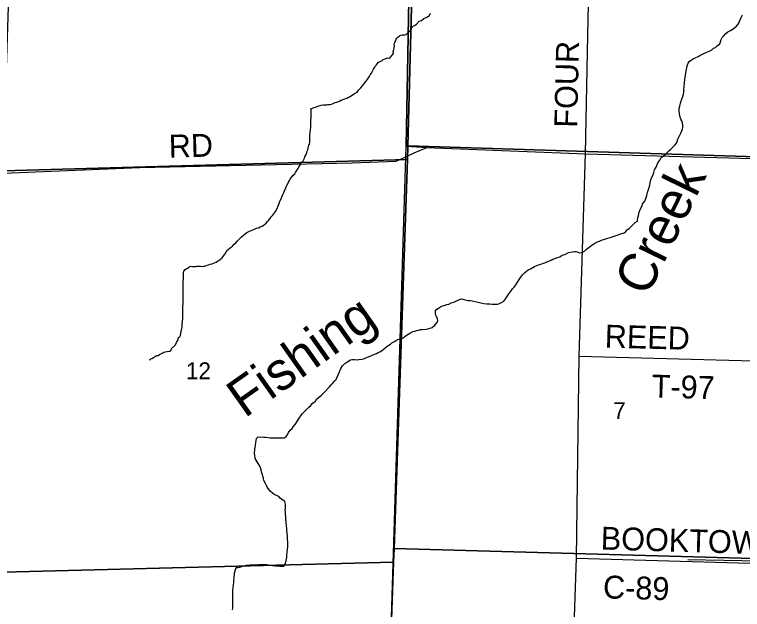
# Model space of a CAD drawing. Extents: x 1588073 to 2013523, y 1090242 to 1357120.
# Drawn here: x 1775971 to 1785512, y 1238801 to 1246602 of the extents above; entities that cross this region are included whole.
import ezdxf

# ---------------------------------------------------------------- set-up
doc = ezdxf.new("R2010")
doc.units = 0
for name, color, linetype in [('GM_X_County_Road', 7, 'Continuous'), ('GM_X_County_Road_Text', 7, 'Continuous'), ('GM_X_Minor_River', 7, 'Continuous'), ('GM_X_Minor_River_Text', 7, 'Continuous'), ('GM_X_Section', 7, 'Continuous'), ('GM_X_Section_Text', 7, 'Continuous'), ('GM_X_Township', 7, 'Continuous'), ('GM_X_Township_Road', 7, 'Continuous'), ('GM_X_Township_Road_Text', 7, 'Continuous')]:
    doc.layers.add(name, color=color, linetype=linetype)

msp = doc.modelspace()

# ---------------------------------------------------------------- linework, layer by layer
at = {"layer": 'GM_X_County_Road'}
for points in [[(1783454.6, 1244777.1), (1783483.6, 1246333.5), (1783512.5, 1247549.2), (1783520.4, 1247879.8), (1783535, 1248540.5), (1783603.1, 1249160.2), (1783630.9, 1249895)], [(1781100, 1244734.5), (1781211, 1244789.1), (1781374.5, 1244858.9), (1783454.6, 1244777.1)], [(1783121.2, 1229450.4), (1783155.4, 1234094.4), (1783337.6, 1239471.4), (1783374, 1242120.5), (1783454.6, 1244777.1)], [(1783454.6, 1244777.1), (1789714, 1244599.1), (1794098.9, 1244507.8)], [(1773346.4, 1244497.8), (1775825.4, 1244523.5), (1777610.5, 1244596.7), (1780396.8, 1244658.8), (1780972.6, 1244678.2), (1781100, 1244734.5)], [(1783337.6, 1239471.4), (1786668.9, 1239378.6), (1793915.9, 1239279.6)]]:
    msp.add_lwpolyline(points, dxfattribs=at)
at = {"layer": 'GM_X_Minor_River'}
msp.add_line((1787914.9, 1239390.1), (1784794.5, 1239452.2), dxfattribs=at)
for points in [[(1780699.6, 1245923.9), (1780713.6, 1245942), (1780725.6, 1245956.1), (1780737.5, 1245974.2), (1780751.5, 1245982.3), (1780765.5, 1245986.3), (1780789.5, 1245998.4), (1780801.5, 1246014.5), (1780865.4, 1246032.8), (1780881.4, 1246030.8), (1780895.4, 1246040.9), (1780925.4, 1246073.1), (1780937.3, 1246091.2), (1780935.3, 1246111.2), (1780937.2, 1246125.3), (1780943.2, 1246149.4), (1780945.1, 1246165.4), (1780949.1, 1246187.5), (1780949, 1246207.6), (1780953, 1246225.6), (1780958.9, 1246243.7), (1780962.9, 1246257.7), (1780972.8, 1246277.8), (1780980.8, 1246291.9), (1780992.8, 1246306), (1781014.7, 1246322.1), (1781032.7, 1246332.2), (1781052.7, 1246338.2), (1781086.8, 1246334.3), (1781104.7, 1246340.4), (1781142.7, 1246378.6), (1781160.6, 1246392.8), (1781172.6, 1246410.8), (1781176.5, 1246432.9), (1781196.5, 1246451), (1781220.5, 1246461.1), (1781238.5, 1246477.2), (1781256.4, 1246495.3), (1781266.4, 1246509.4), (1781288.4, 1246519.5), (1781306.4, 1246525.6), (1781334.3, 1246551.8), (1781376.3, 1246567.9), (1781396.3, 1246580), (1781410.2, 1246590.1), (1781424.2, 1246620.2)], [(1784470.9, 1244743.8), (1784497.1, 1244767.7), (1784519.2, 1244787.7), (1784549.5, 1244817.6), (1784569.6, 1244833.5), (1784595.8, 1244857.4), (1784626, 1244889.3), (1784646.2, 1244915.2), (1784658.4, 1244937.2), (1784664.6, 1244967.3), (1784691, 1245021.3), (1784705.2, 1245045.3), (1784719.4, 1245075.3), (1784727.5, 1245097.3), (1784731.7, 1245123.3), (1784731.9, 1245151.4), (1784728.1, 1245183.6), (1784716.3, 1245209.7), (1784704.4, 1245231.8), (1784694.6, 1245258), (1784686.8, 1245298.2), (1784683.1, 1245340.3), (1784683.3, 1245376.4), (1784689.5, 1245400.5), (1784699.8, 1245438.5), (1784705.9, 1245458.5), (1784718.1, 1245490.6), (1784730.4, 1245528.6), (1784738.6, 1245556.6), (1784742.8, 1245584.7), (1784745, 1245616.8), (1784749.3, 1245656.9), (1784753.6, 1245703), (1784757.9, 1245753.1), (1784764.3, 1245801.2), (1784768.5, 1245843.3), (1784776.8, 1245879.4), (1784783, 1245911.4), (1784791.2, 1245941.5), (1784801.4, 1245965.5), (1784815.6, 1245987.5), (1784871.9, 1246025.2), (1784891.9, 1246033.1), (1784930.1, 1246050.9), (1784952.2, 1246066.8), (1785014.5, 1246094.5), (1785046.6, 1246110.4), (1785068.7, 1246118.3), (1785104.9, 1246136.1), (1785131.1, 1246160), (1785159.2, 1246171.8), (1785181.3, 1246189.8), (1785215.6, 1246219.6), (1785225.7, 1246243.6), (1785232, 1246273.7), (1785246.1, 1246299.7), (1785262.3, 1246319.6), (1785294.6, 1246355.6), (1785322.7, 1246373.4), (1785356.9, 1246393.3), (1785389.1, 1246415.1), (1785415.3, 1246435), (1785435.4, 1246450.9), (1785455.6, 1246474.9), (1785469.7, 1246498.9), (1785479.9, 1246522.9), (1785492.1, 1246552.9), (1785504.3, 1246578.9), (1785514.5, 1246598.9)], [(1779336.2, 1243947.9), (1779354.1, 1243968), (1779366.1, 1243984.1), (1779380, 1244002.2), (1779392, 1244020.3), (1779411.9, 1244060.5), (1779425.8, 1244092.6), (1779437.7, 1244124.8), (1779449.7, 1244154.9), (1779465.6, 1244187), (1779477.5, 1244219.1), (1779489.5, 1244241.2), (1779501.4, 1244269.4), (1779509.3, 1244291.5), (1779525.2, 1244327.6), (1779535.2, 1244349.7), (1779545.1, 1244369.8), (1779553.1, 1244383.9), (1779563.1, 1244404), (1779573, 1244426.1), (1779583, 1244442.1), (1779616.9, 1244492.4), (1779642.8, 1244514.5), (1779652.8, 1244528.6), (1779662.7, 1244544.7), (1779676.7, 1244564.8), (1779688.7, 1244582.9), (1779698.6, 1244605), (1779712.6, 1244627.1), (1779718.5, 1244651.2), (1779736.5, 1244663.3), (1779750.4, 1244675.3), (1779772.3, 1244719.5), (1779774.3, 1244735.6), (1779790.2, 1244757.7), (1779798.2, 1244777.8), (1779802.2, 1244791.8), (1779806.1, 1244809.9), (1779814.1, 1244828), (1779820, 1244848.1), (1779826, 1244870.1), (1779829.9, 1244890.2), (1779835.9, 1244904.3), (1779839.8, 1244926.3), (1779839.6, 1245010.6), (1779841.6, 1245028.6), (1779845.5, 1245048.7), (1779847.5, 1245062.8), (1779849.4, 1245086.8), (1779851.4, 1245100.9), (1779853.3, 1245116.9), (1779855.3, 1245135), (1779855, 1245229.3), (1779857, 1245243.3), (1779857, 1245261.4), (1779860.9, 1245289.5), (1779860.8, 1245305.5), (1779860.8, 1245321.6), (1779860.8, 1245335.6), (1779858.7, 1245351.6), (1779852.7, 1245367.7), (1779884.7, 1245377.8), (1779914.7, 1245385.9), (1779960.6, 1245406.1), (1779988.6, 1245414.2), (1780018.6, 1245416.3), (1780034.6, 1245418.4), (1780062.7, 1245418.5), (1780078.6, 1245420.5), (1780104.7, 1245424.6), (1780124.7, 1245428.7), (1780146.6, 1245434.8), (1780172.6, 1245448.9), (1780194.6, 1245453), (1780208.6, 1245457.1), (1780228.6, 1245467.1), (1780252.6, 1245477.2), (1780288.6, 1245491.4), (1780326.5, 1245507.6), (1780346.5, 1245517.6), (1780362.5, 1245523.7), (1780382.5, 1245537.8), (1780412.5, 1245556), (1780428.4, 1245566.1), (1780442.4, 1245574.1), (1780460.4, 1245586.2), (1780480.4, 1245610.3), (1780494.3, 1245624.4), (1780510.3, 1245640.5), (1780532.2, 1245668.7), (1780560.1, 1245702.9), (1780576.1, 1245723), (1780592.1, 1245745.1), (1780610, 1245771.2), (1780620, 1245787.3), (1780633.9, 1245809.4), (1780649.8, 1245835.5), (1780661.8, 1245857.6), (1780675.7, 1245883.8), (1780691.7, 1245909.9), (1780699.6, 1245923.9)], [(1781730.9, 1242831.3), (1781811.3, 1242870.9), (1781833.3, 1242872.8), (1781861.3, 1242864.6), (1781891.3, 1242858.4), (1781917.3, 1242854.2), (1781943.3, 1242852), (1781967.3, 1242845.8), (1781987.3, 1242841.7), (1782063.3, 1242825.2), (1782123.3, 1242812.8), (1782163.3, 1242808.5), (1782199.3, 1242806.3), (1782227.3, 1242804.1), (1782269.4, 1242803.8), (1782305.4, 1242805.6), (1782329.5, 1242811.4), (1782355.6, 1242825.3), (1782383.8, 1242845.2), (1782410, 1242877.1), (1782424.2, 1242899.1), (1782448.5, 1242939.1), (1782464.6, 1242959.1), (1782480.8, 1242981), (1782499, 1243003), (1782521.2, 1243028.9), (1782543.4, 1243058.9), (1782565.6, 1243090.8), (1782581.8, 1243118.8), (1782594, 1243138.8), (1782630.4, 1243188.7), (1782658.6, 1243218.6), (1782704.9, 1243252.4), (1782733, 1243268.3), (1782785.2, 1243296.1), (1782853.5, 1243325.7), (1782883.6, 1243333.6), (1782903.7, 1243343.4), (1782923.8, 1243347.3), (1782947.9, 1243361.2), (1782984, 1243373), (1783006.1, 1243382.9), (1783026.2, 1243392.8), (1783054.3, 1243402.7), (1783086.4, 1243414.5), (1783116.5, 1243426.4), (1783136.6, 1243438.3), (1783160.7, 1243452.2), (1783184.8, 1243456), (1783233, 1243481.8), (1783281.1, 1243489.5), (1783311.2, 1243495.3), (1783331.2, 1243493.2), (1783353.2, 1243485.1), (1783379.1, 1243476.9), (1783409.2, 1243482.7), (1783441.4, 1243500.5), (1783467.6, 1243524.4), (1783501.8, 1243550.3), (1783540, 1243578.2), (1783578.2, 1243602), (1783612.4, 1243619.8), (1783640.5, 1243631.7), (1783666.6, 1243641.6), (1783722.8, 1243661.2), (1783805.1, 1243688.8), (1783855.2, 1243706.6), (1783919.4, 1243724.2), (1783959.6, 1243738), (1783981.7, 1243755.9), (1784005.9, 1243781.8), (1784028.1, 1243797.7), (1784066.3, 1243833.6), (1784106.6, 1243873.5), (1784136.8, 1243891.3), (1784136.9, 1243911.4), (1784141.1, 1243935.4), (1784155.4, 1243983.5), (1784157.6, 1244011.6), (1784165.8, 1244031.6), (1784184.1, 1244071.6), (1784198.2, 1244095.6), (1784202.4, 1244119.6), (1784234.7, 1244155.5), (1784251, 1244201.6), (1784259.2, 1244229.6), (1784263.3, 1244249.6), (1784265.5, 1244269.7), (1784279.8, 1244309.7), (1784300.2, 1244365.8), (1784304.3, 1244389.8), (1784308.5, 1244419.9), (1784320.8, 1244457.9), (1784341.1, 1244503.9), (1784351.3, 1244529.9), (1784359.5, 1244564), (1784379.8, 1244600), (1784404.2, 1244656), (1784428.5, 1244691.9), (1784446.7, 1244725.9), (1784470.9, 1244743.8)], [(1777742.3, 1242069.5), (1777748.3, 1242083.5), (1777768.3, 1242093.6), (1777794.3, 1242105.7), (1777832.2, 1242129.9), (1777852.2, 1242132), (1777872.2, 1242142.1), (1777898.2, 1242158.2), (1777930.1, 1242174.3), (1777946.1, 1242180.4), (1777972.1, 1242184.5), (1777994.1, 1242186.6), (1778012.1, 1242188.6), (1778022.1, 1242202.7), (1778030, 1242224.8), (1778066, 1242257), (1778080, 1242269.1), (1778093.9, 1242301.2), (1778115.8, 1242335.4), (1778121.7, 1242365.5), (1778137.7, 1242377.6), (1778147.7, 1242391.7), (1778151.6, 1242423.8), (1778155.5, 1242443.8), (1778165.4, 1242484), (1778169.4, 1242508.1), (1778169.3, 1242546.2), (1778173.2, 1242578.3), (1778175.1, 1242618.4), (1778177, 1242656.5), (1778174.9, 1242688.6), (1778174.7, 1242746.8), (1778178.7, 1242778.9), (1778180.6, 1242807), (1778180.5, 1242835.1), (1778182.4, 1242863.1), (1778182.3, 1242931.3), (1778180.2, 1242951.4), (1778180.2, 1242971.5), (1778182.1, 1242989.5), (1778180.1, 1243011.6), (1778182, 1243035.6), (1778181.8, 1243117.9), (1778183.7, 1243131.9), (1778183.6, 1243184.1), (1778185.6, 1243202.1), (1778187.5, 1243218.2), (1778191.5, 1243236.3), (1778205.4, 1243258.4), (1778263.3, 1243292.6), (1778281.3, 1243300.7), (1778301.4, 1243298.8), (1778345.4, 1243298.9), (1778359.4, 1243301), (1778375.4, 1243303), (1778393.4, 1243301.1), (1778407.4, 1243301.1), (1778427.4, 1243299.2), (1778441.4, 1243301.2), (1778459.4, 1243301.3), (1778475.4, 1243307.4), (1778495.4, 1243315.4), (1778511.4, 1243321.5), (1778535.4, 1243327.6), (1778561.4, 1243331.7), (1778577.4, 1243339.8), (1778591.4, 1243345.8), (1778615.4, 1243355.9), (1778631.3, 1243366), (1778649.3, 1243376.1), (1778671.3, 1243396.2), (1778691.3, 1243410.3), (1778715.2, 1243442.5), (1778729.1, 1243460.6), (1778741.1, 1243476.7), (1778755, 1243508.8), (1778771, 1243522.9), (1778803, 1243545.1), (1778826.9, 1243565.2), (1778850.9, 1243591.4), (1778870.8, 1243609.5), (1778890.8, 1243631.6), (1778914.7, 1243657.8), (1778940.7, 1243681.9), (1778976.6, 1243714.1), (1779014.5, 1243742.3), (1779048.5, 1243760.5), (1779074.5, 1243770.6), (1779094.5, 1243780.7), (1779116.5, 1243788.8), (1779140.4, 1243798.9), (1779168.4, 1243807), (1779192.4, 1243817.1), (1779214.4, 1243827.2), (1779232.4, 1243839.3), (1779246.4, 1243847.3), (1779270.3, 1243867.5), (1779288.3, 1243887.6), (1779300.3, 1243901.7), (1779318.2, 1243923.8), (1779336.2, 1243947.9)], [(1779258.3, 1241061.5), (1779294.3, 1241055.2), (1779322.3, 1241053.1), (1779388.4, 1241052.6), (1779408.4, 1241050.5), (1779438.4, 1241052.3), (1779466.4, 1241050.1), (1779486.5, 1241052), (1779506.5, 1241051.9), (1779530.6, 1241067.8), (1779548.8, 1241091.8), (1779563, 1241121.7), (1779583.2, 1241149.7), (1779609.4, 1241175.6), (1779623.6, 1241195.6), (1779647.8, 1241225.5), (1779666, 1241253.5), (1779678.2, 1241273.5), (1779692.3, 1241297.5), (1779708.5, 1241321.4), (1779722.7, 1241341.4), (1779740.8, 1241365.4), (1779761, 1241387.3), (1779785.2, 1241411.2), (1779829.5, 1241453.1), (1779853.7, 1241477), (1779871.9, 1241503), (1779916.2, 1241532.8), (1779934.4, 1241560.8), (1779992.8, 1241608.5), (1780017, 1241634.4), (1780047.2, 1241664.3), (1780081.5, 1241702.3), (1780101.6, 1241722.2), (1780119.8, 1241744.1), (1780139.9, 1241762.1), (1780170.2, 1241798), (1780184.4, 1241818), (1780196.5, 1241837.9), (1780214.8, 1241875.9), (1780227, 1241908), (1780249.4, 1241960), (1780269.7, 1241996), (1780301.9, 1242025.9), (1780340.1, 1242051.7), (1780374.3, 1242073.5), (1780400.4, 1242079.4), (1780428.4, 1242077.2), (1780464.4, 1242075), (1780484.5, 1242078.9), (1780522.5, 1242080.6), (1780550.6, 1242086.5), (1780576.7, 1242098.3), (1780596.8, 1242108.2), (1780632.9, 1242124.1), (1780657, 1242133.9), (1780713.3, 1242157.7), (1780737.4, 1242169.5), (1780757.4, 1242177.4), (1780781.6, 1242191.3), (1780825.8, 1242225.1), (1780856, 1242251.1), (1780898.3, 1242280.9), (1780918.4, 1242296.8), (1780950.6, 1242316.6), (1780970.7, 1242328.6), (1780996.8, 1242340.4), (1781020.9, 1242348.3), (1781047, 1242356.2), (1781067, 1242364.1), (1781087.2, 1242382), (1781115.3, 1242399.9), (1781139.5, 1242415.8), (1781161.6, 1242429.7), (1781189.7, 1242443.5), (1781215.8, 1242451.4), (1781241.9, 1242457.2), (1781265.9, 1242465.1), (1781294, 1242473), (1781320.1, 1242472.8), (1781366.1, 1242476.5), (1781386.2, 1242480.4), (1781420.3, 1242488.2), (1781444.4, 1242498.1), (1781478.6, 1242528), (1781510.9, 1242561.9), (1781521.1, 1242587.9), (1781513.2, 1242612), (1781501.4, 1242642.2), (1781489.6, 1242670.3), (1781487.7, 1242690.4), (1781489.9, 1242716.5), (1781506, 1242736.4), (1781526.2, 1242752.3), (1781552.3, 1242768.2), (1781578.4, 1242780.1), (1781602.5, 1242788), (1781636.6, 1242797.8), (1781662.7, 1242805.6), (1781692.8, 1242819.5), (1781730.9, 1242831.3)], [(1778828.7, 1238795.3), (1778830.9, 1238821.3), (1778833, 1238843.4), (1778833.2, 1238863.4), (1778833.6, 1238923.6), (1778833.9, 1238971.8), (1778832.1, 1238997.9), (1778832.5, 1239062.1), (1778838.8, 1239114.2), (1778843.1, 1239158.3), (1778845.3, 1239182.3), (1778847.5, 1239204.4), (1778851.6, 1239232.5), (1778853.8, 1239256.5), (1778856, 1239278.6), (1778862.1, 1239302.6), (1778868.3, 1239324.6), (1778876.4, 1239348.6), (1778902.5, 1239352.5), (1778924.6, 1239356.4), (1778948.6, 1239364.2), (1779006.8, 1239381.9), (1779052.9, 1239387.7), (1779099, 1239387.4), (1779167.1, 1239390.9), (1779201.1, 1239388.7), (1779231.1, 1239388.5), (1779251.2, 1239390.4), (1779271.2, 1239390.3), (1779321.2, 1239379.9), (1779353.2, 1239377.7), (1779387.2, 1239373.5), (1779421.2, 1239371.3), (1779449.3, 1239369.1), (1779479.3, 1239366.9), (1779501.3, 1239368.8), (1779521.6, 1239402.8), (1779538.1, 1239480.9), (1779538.2, 1239503), (1779542.6, 1239555.1), (1779551, 1239623.2), (1779553.3, 1239655.3), (1779553.4, 1239677.4), (1779549.7, 1239727.6), (1779548, 1239759.7), (1779538.5, 1239840), (1779538.6, 1239860.1), (1779534.9, 1239898.2), (1779531.1, 1239940.3), (1779527.4, 1239978.5), (1779525.6, 1240016.6), (1779523.9, 1240052.7), (1779522, 1240078.8), (1779520.2, 1240102.9), (1779522.3, 1240123), (1779524.5, 1240153), (1779522.7, 1240181.1), (1779512.9, 1240215.3), (1779451.2, 1240261.8), (1779433.3, 1240282), (1779375.4, 1240308.4), (1779351.5, 1240324.6), (1779321.6, 1240350.9), (1779297.8, 1240383.2), (1779283.9, 1240405.3), (1779272.1, 1240427.5), (1779258.2, 1240451.6), (1779240.4, 1240489.8), (1779232.6, 1240518), (1779224.8, 1240548.1), (1779219, 1240572.2), (1779209.2, 1240602.4), (1779201.3, 1240632.5), (1779193.5, 1240656.7), (1779179.7, 1240686.8), (1779165.8, 1240713), (1779124.2, 1240781.5), (1779118.5, 1240825.6), (1779116.7, 1240847.7), (1779119, 1240899.9), (1779123.2, 1240929.9), (1779127.4, 1240956), (1779133.6, 1240988), (1779137.8, 1241018.1), (1779144, 1241044.1), (1779166.2, 1241062.1), (1779190.2, 1241061.9), (1779218.2, 1241063.7), (1779238.2, 1241061.6), (1779258.3, 1241061.5)]]:
    msp.add_lwpolyline(points, dxfattribs=at)
at = {"layer": 'GM_X_Section'}
for points in [[(1781261.5, 1250000.7), (1781124.6, 1244880.7), (1781123.2, 1244700.6), (1775823, 1244552.7), (1776000.9, 1250072.6)], [(1786253.4, 1249852.8), (1786110.3, 1244724.8), (1781124.6, 1244880.7), (1781261.5, 1250000.7)], [(1781124.6, 1244880.7), (1786110.3, 1244724.8), (1785968.2, 1239458.7), (1780948.4, 1239599), (1781123.2, 1244700.6)], [(1775823, 1244552.7), (1781123.2, 1244700.6), (1780948.4, 1239599), (1780939, 1239420.9), (1775653, 1239287)], [(1785968.2, 1239458.7), (1785757.6, 1234139.3), (1780754.9, 1234157.3), (1780939, 1239420.9), (1780948.4, 1239599)], [(1780939, 1239420.9), (1780754.9, 1234157.3), (1780748.6, 1234119.3), (1775456.7, 1233993.5), (1775653, 1239287)]]:
    msp.add_lwpolyline(points, close=True, dxfattribs=at)
at = {"layer": 'GM_X_Township'}
for points in [[(1786336.9, 1260386.3), (1783657.7, 1260404.7), (1783297.9, 1260406), (1782450.2, 1260413.4), (1781290.9, 1260418.2), (1781295.9, 1257972.1), (1781293.6, 1257698.9), (1781293.1, 1255294.3), (1781244.3, 1252600.3), (1781193.8, 1249809.6), (1781165.4, 1248243.1), (1781104.5, 1244875.1), (1781374.5, 1244858.9), (1783454.6, 1244777.1), (1789714, 1244599.1)], [(1780849.5, 1236733), (1781100, 1244734.5), (1781104.5, 1244875.1), (1781165.4, 1248243.1)], [(1780849.5, 1236733), (1781100, 1244734.5), (1781104.5, 1244875.1), (1781374.5, 1244858.9), (1783454.6, 1244777.1), (1789714, 1244599.1), (1794098.9, 1244507.9), (1797984.2, 1244413.4), (1801960.9, 1244391.9)]]:
    msp.add_lwpolyline(points, dxfattribs=at)
at = {"layer": 'GM_X_Township_Road'}
for points in [[(1780849.5, 1236733), (1781100, 1244734.5)], [(1783374, 1242120.5), (1793989.1, 1241838.3)]]:
    msp.add_lwpolyline(points, dxfattribs=at)

# ---------------------------------------------------------------- texts
at = {"layer": 'GM_X_County_Road_Text'}
for s, rotation, p in [('FOUR', 88.71045, (1783345.5, 1245116)), ('RD', 1.48068, (1777995.8, 1244725.3)), ('BOOKTOWN', 358.34997, (1783651.9, 1239586.2)), ('C-89', 358.2847, (1783681.3, 1238947.2))]:
    msp.add_text(s, height=300, rotation=rotation, dxfattribs=at).set_placement(p)
at = {"layer": 'GM_X_Minor_River_Text'}
for s, height, rotation, p in [('Creek', 500.32, 63.93728, (1784264.4, 1242888.2)), ('Fishing', 500.3, 35.21788, (1778987, 1241302.9))]:
    msp.add_text(s, height=height, rotation=rotation, dxfattribs=at).set_placement(p)
at = {"layer": 'GM_X_Section_Text'}
for s, p in [('12', (1778216.7, 1241819.7)), ('7', (1783817.9, 1241297.2))]:
    msp.add_text(s, height=221, rotation=0.00001, dxfattribs=at).set_placement(p)
at = {"layer": 'GM_X_Township_Road_Text'}
for s, rotation, p in [('REED', 358.42333, (1783704.4, 1242235.6)), ('T-97', 358.47707, (1784320.2, 1241580.6))]:
    msp.add_text(s, height=300, rotation=rotation, dxfattribs=at).set_placement(p)

doc.saveas('drawing.dxf')
